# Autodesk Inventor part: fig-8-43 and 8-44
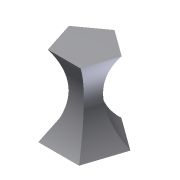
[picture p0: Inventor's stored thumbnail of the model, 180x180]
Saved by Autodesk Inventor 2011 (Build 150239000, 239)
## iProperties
Shininess: 64.0
Length Units: 11269
Angle Units: 11279
Time Units: 11290
Mass Units: 11283
Length Display Precision: 3
Angle Display Precision: 2
Compacted: True
Part Number: fig-8-43 and 8-44
Document SubType Name: Modeling
Created: 2002-12
Designer: deepak
Density: 1 g/cm^3
Density: 0.0
Volumn: 0.0
Area: 0.0
PropertySet Name: Model Information
Control State: 0
Master: False
Checked Out: False
Author: deepak
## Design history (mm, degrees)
sketch "Sketch1"
  geometry: L1 (0, 21.819)-(20.751, 6.743); L2 (20.751, 6.743)-(12.825, -17.652); L3 (12.825, -17.652)-(-12.825, -17.652); L4 (-12.825, -17.652)-(-20.751, 6.743); L5 (-20.751, 6.743)-(0, 21.819); 1 further point
  constraints: 10 end point, 9 other
workplane "Work Plane1"
sketch "Sketch2"
  geometry: L1 (0, 8.24)-(7.836, 2.546); L2 (7.836, 2.546)-(4.843, -6.666); L3 (4.843, -6.666)-(-4.843, -6.666); L4 (-4.843, -6.666)-(-7.836, 2.546); L5 (-7.836, 2.546)-(0, 8.24); 1 further point
  constraints: 10 end point, 9 other
workplane "Work Plane2"
sketch "Sketch3"
  geometry: L1 (0, 17.494)-(16.637, 5.406); L2 (16.637, 5.406)-(10.283, -14.153); L3 (10.283, -14.153)-(-10.283, -14.153); L4 (-10.283, -14.153)-(-16.637, 5.406); L5 (-16.637, 5.406)-(0, 17.494); 1 further point
  constraints: 10 end point, 9 other
loft "Loft4" sketch "Sketch3" dims "d20" = 0, "d21" = 90 deg, "d22" = 0, "d23" = 90 deg, "d24" = 0, "d25" = 90 deg
body "Solid1"
other parameters: "d0" = 25, "d1" = 25
